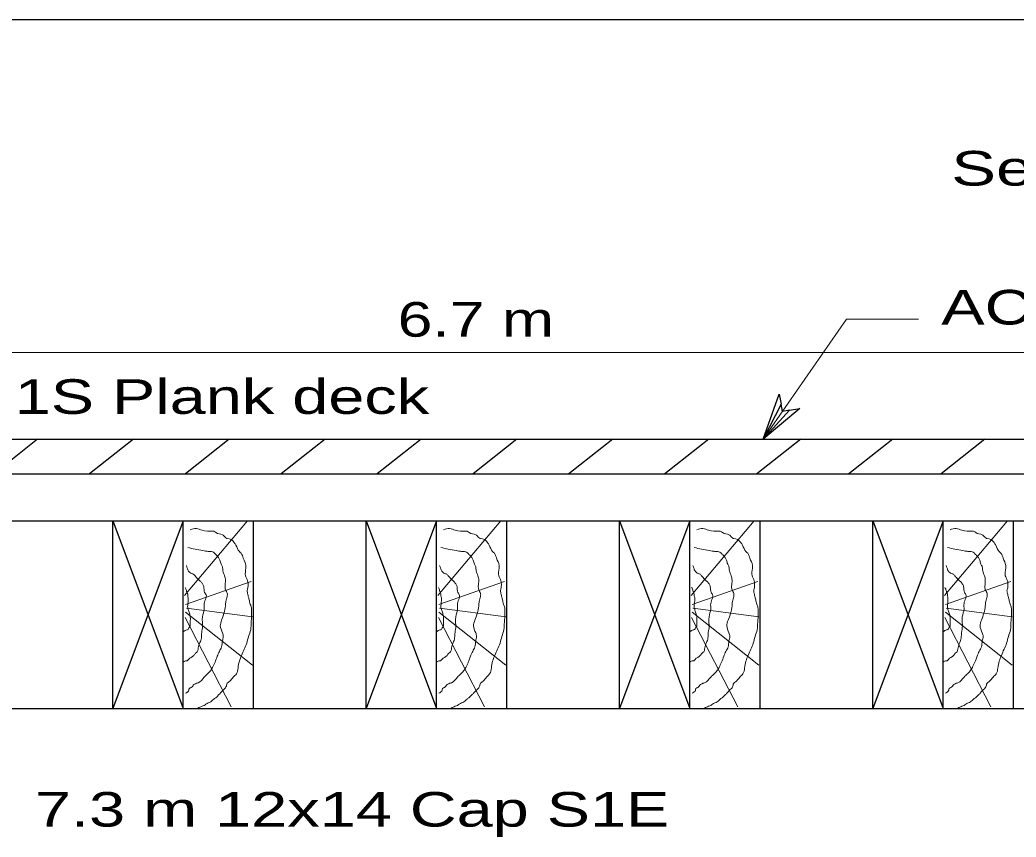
# Model space of a CAD drawing. Extents: x 13426 to 15509, y -9298 to -5111.
# Drawn here: x 15412 to 15449.6, y -5410.66 to -5379.81 of the extents above; entities that cross this region are included whole.
import ezdxf
from ezdxf.enums import TextEntityAlignment as Align

# ---------------------------------------------------------------- set-up
doc = ezdxf.new("R2010")
doc.units = 0
doc.header["$LTSCALE"] = 0.52
for name, color, linetype, lineweight in [('1', 7, 'Continuous', 13), ('15', 7, 'Continuous', 13), ('16', 7, 'Continuous', 25), ('20', 7, 'Continuous', 13), ('30', 7, 'Continuous', 25), ('4', 7, 'Continuous', 13)]:
    doc.layers.add(name, color=color, linetype=linetype, lineweight=lineweight)
doc.layers.add('19', color=7, linetype='Continuous')

msp = doc.modelspace()

# ---------------------------------------------------------------- linework, layer by layer
at = {"layer": '1', "lineweight": 25}
msp.add_line((15363.992, -5405.801), (15491.456, -5405.801), dxfattribs=at)
at = {"layer": '15'}
for p, q in [((15443.201, -5391.101), (15440.058, -5395.631)), ((15445.917, -5391.101), (15443.201, -5391.101)), ((15486.643, -5392.358), (15368.805, -5392.358))]:
    msp.add_line(p, q, dxfattribs=at)
at = {"layer": '16'}
msp.add_lwpolyline([(15441.051, -5394.537), (15441.436, -5394.475), (15440.058, -5395.631), (15440.658, -5393.936), (15440.736, -5394.319), (15440.058, -5395.631), (15441.051, -5394.537), (15440.784, -5394.585), (15440.736, -5394.319)], dxfattribs=at)
at = {"layer": '30'}
msp.add_line((15509.151, -5379.809), (15181.119, -5379.809), dxfattribs=at)
at = {"layer": '4', "lineweight": 25}
for p, q in [((15368.805, -5395.631), (15486.643, -5395.631)), ((15412.664, -5395.631), (15411.007, -5396.949)), ((15416.283, -5395.631), (15414.626, -5396.949)), ((15419.903, -5395.631), (15418.246, -5396.949)), ((15423.522, -5395.631), (15421.865, -5396.949)), ((15427.141, -5395.631), (15425.485, -5396.949)), ((15430.761, -5395.631), (15429.104, -5396.949)), ((15434.38, -5395.631), (15432.723, -5396.949)), ((15438, -5395.631), (15436.343, -5396.949)), ((15441.474, -5395.631), (15439.817, -5396.949)), ((15444.949, -5395.631), (15443.292, -5396.949)), ((15448.423, -5395.631), (15446.766, -5396.949)), ((15369.303, -5398.72), (15486.145, -5398.72)), ((15415.509, -5405.801), (15415.509, -5398.72)), ((15415.509, -5398.72), (15418.164, -5405.801)), ((15418.164, -5398.72), (15415.509, -5405.801)), ((15418.164, -5405.801), (15418.164, -5398.72)), ((15420.82, -5405.801), (15420.82, -5398.72)), ((15425.068, -5405.801), (15425.068, -5398.72)), ((15425.068, -5398.72), (15427.724, -5405.801)), ((15427.724, -5398.72), (15425.068, -5405.801)), ((15427.724, -5405.801), (15427.724, -5398.72)), ((15430.38, -5405.801), (15430.38, -5398.72)), ((15434.628, -5405.801), (15434.628, -5398.72)), ((15434.628, -5398.72), (15437.284, -5405.801)), ((15437.284, -5398.72), (15434.628, -5405.801)), ((15437.284, -5405.801), (15437.284, -5398.72)), ((15439.939, -5405.801), (15439.939, -5398.72)), ((15444.188, -5405.801), (15444.188, -5398.72)), ((15444.188, -5398.72), (15446.844, -5405.801)), ((15446.844, -5398.72), (15444.188, -5405.801)), ((15446.844, -5405.801), (15446.844, -5398.72)), ((15449.499, -5405.801), (15449.499, -5398.72))]:
    msp.add_line(p, q, dxfattribs=at)
at = {"layer": '4'}
for p, q in [((15420.595, -5398.719), (15418.217, -5401.539)), ((15430.155, -5398.719), (15427.777, -5401.539)), ((15439.715, -5398.719), (15437.336, -5401.539)), ((15449.274, -5398.719), (15446.896, -5401.539)), ((15420.726, -5401.013), (15418.249, -5401.879)), ((15430.286, -5401.013), (15427.809, -5401.879)), ((15439.846, -5401.013), (15437.369, -5401.879)), ((15449.406, -5401.013), (15446.929, -5401.879)), ((15420.776, -5404.172), (15418.249, -5402.168)), ((15420.776, -5402.337), (15418.282, -5402.015)), ((15430.336, -5404.172), (15427.809, -5402.168)), ((15430.336, -5402.337), (15427.842, -5402.015)), ((15439.895, -5404.172), (15437.369, -5402.168)), ((15439.895, -5402.337), (15437.402, -5402.015)), ((15449.455, -5404.172), (15446.929, -5402.168)), ((15449.455, -5402.337), (15446.962, -5402.015)), ((15419.972, -5405.735), (15418.233, -5402.372)), ((15429.532, -5405.735), (15427.793, -5402.372)), ((15439.091, -5405.735), (15437.353, -5402.372)), ((15448.651, -5405.735), (15446.913, -5402.372))]:
    msp.add_line(p, q, dxfattribs=at)
at = {"layer": '4', "lineweight": 25}
msp.add_lwpolyline([(15369.303, -5396.949), (15486.145, -5396.949), (15486.145, -5405.801)], dxfattribs=at)
at = {"layer": '4'}
for points in [[(15418.43, -5399.059), (15418.66, -5399.008), (15418.873, -5399.076), (15419.283, -5399.109), (15419.315, -5399.109), (15419.398, -5399.161), (15419.644, -5399.245), (15419.742, -5399.33), (15419.808, -5399.382), (15419.824, -5399.382), (15420.087, -5399.534), (15420.152, -5399.636), (15420.284, -5399.874), (15420.349, -5399.942), (15420.431, -5400.129), (15420.53, -5400.401), (15420.53, -5400.503), (15420.513, -5400.791), (15420.595, -5400.979), (15420.612, -5401.149), (15420.595, -5401.284), (15420.579, -5401.335), (15420.579, -5401.386), (15420.595, -5401.454), (15420.612, -5401.539), (15420.644, -5401.658), (15420.661, -5401.743), (15420.71, -5401.896), (15420.743, -5402.032), (15420.743, -5402.151), (15420.743, -5402.337), (15420.726, -5402.542), (15420.71, -5402.83), (15420.628, -5403.085), (15420.562, -5403.34), (15420.464, -5403.561), (15420.365, -5403.799), (15420.284, -5404.019), (15420.234, -5404.274), (15420.169, -5404.495), (15420.054, -5404.614), (15419.923, -5404.767), (15419.808, -5404.886), (15419.791, -5404.954), (15419.758, -5405.022), (15419.693, -5405.09), (15419.594, -5405.192), (15419.512, -5405.277), (15419.414, -5405.379), (15419.315, -5405.447), (15419.201, -5405.549), (15419.021, -5405.634), (15418.955, -5405.685), (15418.873, -5405.719), (15418.791, -5405.753), (15418.643, -5405.804), (15418.642, -5405.804)], [(15427.99, -5399.059), (15428.219, -5399.008), (15428.433, -5399.076), (15428.843, -5399.109), (15428.875, -5399.109), (15428.957, -5399.161), (15429.203, -5399.245), (15429.302, -5399.33), (15429.368, -5399.382), (15429.384, -5399.382), (15429.646, -5399.534), (15429.712, -5399.636), (15429.843, -5399.874), (15429.909, -5399.942), (15429.991, -5400.129), (15430.089, -5400.401), (15430.089, -5400.503), (15430.073, -5400.791), (15430.155, -5400.979), (15430.171, -5401.149), (15430.155, -5401.284), (15430.139, -5401.335), (15430.139, -5401.386), (15430.155, -5401.454), (15430.171, -5401.539), (15430.204, -5401.658), (15430.221, -5401.743), (15430.27, -5401.896), (15430.303, -5402.032), (15430.303, -5402.151), (15430.303, -5402.337), (15430.286, -5402.542), (15430.27, -5402.83), (15430.188, -5403.085), (15430.122, -5403.34), (15430.024, -5403.561), (15429.925, -5403.799), (15429.843, -5404.019), (15429.794, -5404.274), (15429.729, -5404.495), (15429.614, -5404.614), (15429.482, -5404.767), (15429.368, -5404.886), (15429.351, -5404.954), (15429.318, -5405.022), (15429.253, -5405.09), (15429.154, -5405.192), (15429.072, -5405.277), (15428.974, -5405.379), (15428.875, -5405.447), (15428.76, -5405.549), (15428.58, -5405.634), (15428.514, -5405.685), (15428.433, -5405.719), (15428.351, -5405.753), (15428.203, -5405.804), (15428.202, -5405.804)], [(15437.55, -5399.059), (15437.779, -5399.008), (15437.993, -5399.076), (15438.402, -5399.109), (15438.435, -5399.109), (15438.517, -5399.161), (15438.763, -5399.245), (15438.862, -5399.33), (15438.927, -5399.382), (15438.944, -5399.382), (15439.206, -5399.534), (15439.272, -5399.636), (15439.403, -5399.874), (15439.469, -5399.942), (15439.551, -5400.129), (15439.649, -5400.401), (15439.649, -5400.503), (15439.633, -5400.791), (15439.715, -5400.979), (15439.731, -5401.149), (15439.715, -5401.284), (15439.698, -5401.335), (15439.698, -5401.386), (15439.715, -5401.454), (15439.731, -5401.539), (15439.764, -5401.658), (15439.781, -5401.743), (15439.829, -5401.896), (15439.863, -5402.032), (15439.863, -5402.151), (15439.863, -5402.337), (15439.846, -5402.542), (15439.829, -5402.83), (15439.748, -5403.085), (15439.682, -5403.34), (15439.584, -5403.561), (15439.485, -5403.799), (15439.403, -5404.019), (15439.354, -5404.274), (15439.288, -5404.495), (15439.174, -5404.614), (15439.042, -5404.767), (15438.927, -5404.886), (15438.911, -5404.954), (15438.878, -5405.022), (15438.813, -5405.09), (15438.714, -5405.192), (15438.632, -5405.277), (15438.534, -5405.379), (15438.435, -5405.447), (15438.32, -5405.549), (15438.14, -5405.634), (15438.074, -5405.685), (15437.993, -5405.719), (15437.911, -5405.753), (15437.763, -5405.804), (15437.762, -5405.804)], [(15447.109, -5399.059), (15447.339, -5399.008), (15447.552, -5399.076), (15447.962, -5399.109), (15447.995, -5399.109), (15448.077, -5399.161), (15448.323, -5399.245), (15448.422, -5399.33), (15448.487, -5399.382), (15448.504, -5399.382), (15448.766, -5399.534), (15448.832, -5399.636), (15448.963, -5399.874), (15449.029, -5399.942), (15449.111, -5400.129), (15449.209, -5400.401), (15449.209, -5400.503), (15449.192, -5400.791), (15449.274, -5400.979), (15449.291, -5401.149), (15449.274, -5401.284), (15449.258, -5401.335), (15449.258, -5401.386), (15449.274, -5401.454), (15449.291, -5401.539), (15449.324, -5401.658), (15449.34, -5401.743), (15449.389, -5401.896), (15449.422, -5402.032), (15449.422, -5402.151), (15449.422, -5402.337), (15449.406, -5402.542), (15449.389, -5402.83), (15449.308, -5403.085), (15449.242, -5403.34), (15449.144, -5403.561), (15449.045, -5403.799), (15448.963, -5404.019), (15448.913, -5404.274), (15448.848, -5404.495), (15448.733, -5404.614), (15448.602, -5404.767), (15448.487, -5404.886), (15448.471, -5404.954), (15448.438, -5405.022), (15448.372, -5405.09), (15448.274, -5405.192), (15448.192, -5405.277), (15448.093, -5405.379), (15447.995, -5405.447), (15447.88, -5405.549), (15447.7, -5405.634), (15447.634, -5405.685), (15447.552, -5405.719), (15447.47, -5405.753), (15447.322, -5405.804), (15447.321, -5405.804)], [(15418.332, -5399.721), (15418.61, -5399.789), (15418.906, -5399.84), (15419.004, -5399.857), (15419.135, -5399.874), (15419.185, -5399.874), (15419.332, -5399.925), (15419.348, -5399.942), (15419.43, -5400.027), (15419.545, -5400.197), (15419.594, -5400.35), (15419.644, -5400.452), (15419.66, -5400.605), (15419.726, -5400.791), (15419.758, -5400.961), (15419.742, -5401.182), (15419.758, -5401.318), (15419.824, -5401.454), (15419.824, -5401.573), (15419.775, -5401.76), (15419.758, -5401.93), (15419.611, -5402.473), (15419.562, -5402.677), (15419.644, -5402.949), (15419.676, -5403.085), (15419.644, -5403.255), (15419.611, -5403.476), (15419.529, -5403.646), (15419.447, -5403.833), (15419.365, -5404.053), (15419.315, -5404.156), (15419.217, -5404.343), (15419.086, -5404.495), (15418.955, -5404.614), (15418.725, -5404.835), (15418.66, -5404.852), (15418.594, -5404.886), (15418.545, -5404.92), (15418.496, -5404.988), (15418.381, -5405.073), (15418.381, -5405.107), (15418.332, -5405.175), (15418.315, -5405.192), (15418.249, -5405.226)], [(15427.891, -5399.721), (15428.17, -5399.789), (15428.465, -5399.84), (15428.564, -5399.857), (15428.695, -5399.874), (15428.744, -5399.874), (15428.892, -5399.925), (15428.908, -5399.942), (15428.99, -5400.027), (15429.105, -5400.197), (15429.154, -5400.35), (15429.203, -5400.452), (15429.22, -5400.605), (15429.286, -5400.791), (15429.318, -5400.961), (15429.302, -5401.182), (15429.318, -5401.318), (15429.384, -5401.454), (15429.384, -5401.573), (15429.335, -5401.76), (15429.318, -5401.93), (15429.171, -5402.473), (15429.121, -5402.677), (15429.203, -5402.949), (15429.236, -5403.085), (15429.203, -5403.255), (15429.171, -5403.476), (15429.089, -5403.646), (15429.007, -5403.833), (15428.925, -5404.053), (15428.875, -5404.156), (15428.777, -5404.343), (15428.646, -5404.495), (15428.514, -5404.614), (15428.285, -5404.835), (15428.219, -5404.852), (15428.154, -5404.886), (15428.105, -5404.92), (15428.055, -5404.988), (15427.941, -5405.073), (15427.941, -5405.107), (15427.891, -5405.175), (15427.875, -5405.192), (15427.809, -5405.226)], [(15437.451, -5399.721), (15437.73, -5399.789), (15438.025, -5399.84), (15438.123, -5399.857), (15438.255, -5399.874), (15438.304, -5399.874), (15438.452, -5399.925), (15438.468, -5399.942), (15438.55, -5400.027), (15438.665, -5400.197), (15438.714, -5400.35), (15438.763, -5400.452), (15438.78, -5400.605), (15438.845, -5400.791), (15438.878, -5400.961), (15438.862, -5401.182), (15438.878, -5401.318), (15438.944, -5401.454), (15438.944, -5401.573), (15438.895, -5401.76), (15438.878, -5401.93), (15438.731, -5402.473), (15438.681, -5402.677), (15438.763, -5402.949), (15438.796, -5403.085), (15438.763, -5403.255), (15438.731, -5403.476), (15438.648, -5403.646), (15438.566, -5403.833), (15438.484, -5404.053), (15438.435, -5404.156), (15438.337, -5404.343), (15438.206, -5404.495), (15438.074, -5404.614), (15437.845, -5404.835), (15437.779, -5404.852), (15437.714, -5404.886), (15437.664, -5404.92), (15437.615, -5404.988), (15437.5, -5405.073), (15437.5, -5405.107), (15437.451, -5405.175), (15437.435, -5405.192), (15437.369, -5405.226)], [(15447.011, -5399.721), (15447.29, -5399.789), (15447.585, -5399.84), (15447.683, -5399.857), (15447.815, -5399.874), (15447.864, -5399.874), (15448.011, -5399.925), (15448.028, -5399.942), (15448.11, -5400.027), (15448.225, -5400.197), (15448.274, -5400.35), (15448.323, -5400.452), (15448.34, -5400.605), (15448.405, -5400.791), (15448.438, -5400.961), (15448.422, -5401.182), (15448.438, -5401.318), (15448.504, -5401.454), (15448.504, -5401.573), (15448.454, -5401.76), (15448.438, -5401.93), (15448.29, -5402.473), (15448.241, -5402.677), (15448.323, -5402.949), (15448.356, -5403.085), (15448.323, -5403.255), (15448.29, -5403.476), (15448.208, -5403.646), (15448.126, -5403.833), (15448.044, -5404.053), (15447.995, -5404.156), (15447.897, -5404.343), (15447.765, -5404.495), (15447.634, -5404.614), (15447.404, -5404.835), (15447.339, -5404.852), (15447.274, -5404.886), (15447.224, -5404.92), (15447.175, -5404.988), (15447.06, -5405.073), (15447.06, -5405.107), (15447.011, -5405.175), (15446.995, -5405.192), (15446.929, -5405.226)], [(15418.282, -5400.401), (15418.315, -5400.503), (15418.364, -5400.622), (15418.479, -5400.706), (15418.528, -5400.724), (15418.61, -5400.791), (15418.725, -5400.928), (15418.824, -5401.013), (15418.889, -5401.097), (15418.938, -5401.199), (15418.971, -5401.42), (15419.037, -5401.539), (15419.021, -5401.641), (15418.955, -5401.845), (15418.955, -5402.049), (15418.889, -5402.337), (15418.889, -5402.762), (15418.856, -5402.983), (15418.84, -5403.187), (15418.774, -5403.357), (15418.725, -5403.561), (15418.692, -5403.663), (15418.627, -5403.714), (15418.561, -5403.799), (15418.364, -5403.952), (15418.315, -5404.003), (15418.282, -5404.003), (15418.167, -5404.053)], [(15427.842, -5400.401), (15427.875, -5400.503), (15427.924, -5400.622), (15428.039, -5400.706), (15428.088, -5400.724), (15428.17, -5400.791), (15428.285, -5400.928), (15428.384, -5401.013), (15428.449, -5401.097), (15428.498, -5401.199), (15428.531, -5401.42), (15428.596, -5401.539), (15428.58, -5401.641), (15428.514, -5401.845), (15428.514, -5402.049), (15428.449, -5402.337), (15428.449, -5402.762), (15428.416, -5402.983), (15428.4, -5403.187), (15428.334, -5403.357), (15428.285, -5403.561), (15428.252, -5403.663), (15428.187, -5403.714), (15428.121, -5403.799), (15427.924, -5403.952), (15427.875, -5404.003), (15427.842, -5404.003), (15427.727, -5404.053)], [(15437.402, -5400.401), (15437.435, -5400.503), (15437.484, -5400.622), (15437.599, -5400.706), (15437.648, -5400.724), (15437.73, -5400.791), (15437.845, -5400.928), (15437.943, -5401.013), (15438.009, -5401.097), (15438.058, -5401.199), (15438.091, -5401.42), (15438.156, -5401.539), (15438.14, -5401.641), (15438.074, -5401.845), (15438.074, -5402.049), (15438.009, -5402.337), (15438.009, -5402.762), (15437.976, -5402.983), (15437.959, -5403.187), (15437.894, -5403.357), (15437.845, -5403.561), (15437.812, -5403.663), (15437.746, -5403.714), (15437.681, -5403.799), (15437.484, -5403.952), (15437.435, -5404.003), (15437.402, -5404.003), (15437.287, -5404.053)], [(15446.962, -5400.401), (15446.995, -5400.503), (15447.044, -5400.622), (15447.159, -5400.706), (15447.208, -5400.724), (15447.29, -5400.791), (15447.404, -5400.928), (15447.503, -5401.013), (15447.569, -5401.097), (15447.618, -5401.199), (15447.651, -5401.42), (15447.716, -5401.539), (15447.7, -5401.641), (15447.634, -5401.845), (15447.634, -5402.049), (15447.569, -5402.337), (15447.569, -5402.762), (15447.536, -5402.983), (15447.519, -5403.187), (15447.454, -5403.357), (15447.404, -5403.561), (15447.372, -5403.663), (15447.306, -5403.714), (15447.24, -5403.799), (15447.044, -5403.952), (15446.995, -5404.003), (15446.962, -5404.003), (15446.847, -5404.053)], [(15418.233, -5401.233), (15418.282, -5401.352), (15418.299, -5401.42), (15418.332, -5401.488), (15418.332, -5401.556), (15418.348, -5401.624), (15418.348, -5401.675), (15418.348, -5401.743), (15418.332, -5401.913), (15418.348, -5402.066), (15418.397, -5402.202), (15418.43, -5402.355), (15418.43, -5402.661), (15418.413, -5402.728), (15418.397, -5402.728), (15418.364, -5402.796), (15418.266, -5402.847), (15418.2, -5402.881), (15418.151, -5402.915)], [(15427.793, -5401.233), (15427.842, -5401.352), (15427.858, -5401.42), (15427.891, -5401.488), (15427.891, -5401.556), (15427.908, -5401.624), (15427.908, -5401.675), (15427.908, -5401.743), (15427.891, -5401.913), (15427.908, -5402.066), (15427.957, -5402.202), (15427.99, -5402.355), (15427.99, -5402.661), (15427.973, -5402.728), (15427.957, -5402.728), (15427.924, -5402.796), (15427.826, -5402.847), (15427.76, -5402.881), (15427.711, -5402.915)], [(15437.353, -5401.233), (15437.402, -5401.352), (15437.418, -5401.42), (15437.451, -5401.488), (15437.451, -5401.556), (15437.468, -5401.624), (15437.468, -5401.675), (15437.468, -5401.743), (15437.451, -5401.913), (15437.468, -5402.066), (15437.517, -5402.202), (15437.55, -5402.355), (15437.55, -5402.661), (15437.533, -5402.728), (15437.517, -5402.728), (15437.484, -5402.796), (15437.386, -5402.847), (15437.32, -5402.881), (15437.271, -5402.915)], [(15446.913, -5401.233), (15446.962, -5401.352), (15446.978, -5401.42), (15447.011, -5401.488), (15447.011, -5401.556), (15447.027, -5401.624), (15447.027, -5401.675), (15447.027, -5401.743), (15447.011, -5401.913), (15447.027, -5402.066), (15447.077, -5402.202), (15447.109, -5402.355), (15447.109, -5402.661), (15447.093, -5402.728), (15447.077, -5402.728), (15447.044, -5402.796), (15446.945, -5402.847), (15446.88, -5402.881), (15446.831, -5402.915)]]:
    msp.add_spline(points, degree=3, dxfattribs=at)

# ---------------------------------------------------------------- texts
at = {"layer": '19', "width": 1.35}
msp.add_text('6.7 m', height=1.307, dxfattribs=at).set_placement((15429.2085, -5391.767), align=Align.CENTER)
at = {"layer": '19', "width": 1.4}
msp.add_text('7.3 m 12x14 Cap S1E', height=1.307, dxfattribs=at).set_placement((15412.57, -5410.262))
at = {"layer": '20', "width": 1.45}
msp.add_text('Service Level 1 Bridge Rail', height=1.307, dxfattribs=at).set_placement((15477.578, -5386.063), align=Align.RIGHT)
at = {"layer": '20', "width": 1.4}
msp.add_text('ACP overlay (see Note 8)', height=1.307, dxfattribs=at).set_placement((15446.778, -5391.308))
msp.add_text('4x12 S1S Plank deck', height=1.307, dxfattribs=at).set_placement((15415.8165, -5394.681), align=Align.CENTER)

doc.saveas('drawing.dxf')
